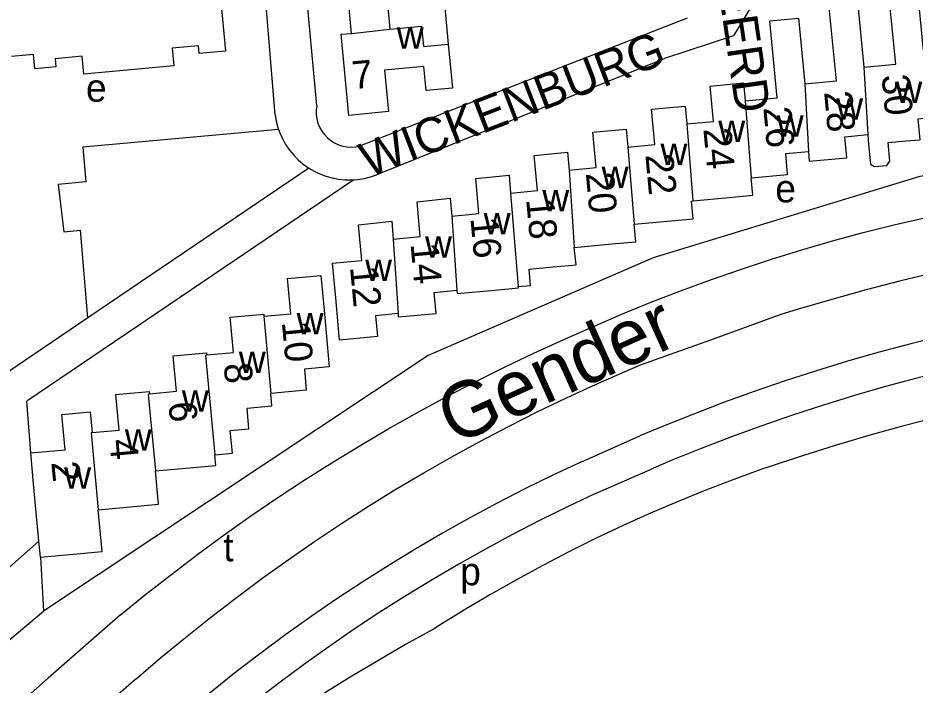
# Model space of a CAD drawing. Extents: x 157794 to 159375, y 380877 to 382306.
# Drawn here: x 158333.5 to 158462.3, y 381095.2 to 381191 of the extents above; entities that cross this region are included whole.
import ezdxf

# ---------------------------------------------------------------- set-up
doc = ezdxf.new("R2010")
doc.units = 0
for name, color, linetype in [('BLT_Basislijn', 7, 'Continuous'), ('BLT_Bebouwing', 7, 'Continuous'), ('BLT_Centroide', 7, 'Continuous'), ('BLT_Huisnummer', 7, 'Continuous'), ('BLT_Huisnummer_ tussenligend', 7, 'Continuous'), ('BLT_Onderverdeling_panden', 7, 'Continuous'), ('BLT_Straatnaam', 7, 'Continuous'), ('BLT_Waternaam_spoorwegen', 7, 'Continuous')]:
    doc.layers.add(name, color=color, linetype=linetype)

msp = doc.modelspace()

# ---------------------------------------------------------------- linework, layer by layer
at = {"layer": 'BLT_Basislijn'}
for p, q in [((158370.4, 381177.07), (158363.87, 381258.34)), ((158376.39, 381178.4), (158369.02, 381258.49)), ((158382.59, 381172.61), (158429.64, 381191.02)), ((158385.64, 381168.75), (158426.34, 381185.15)), ((158375.24, 381169.41), (158343.5, 381147.91)), ((158381.71, 381167.75), (158334.77, 381135.96)), ((158343.5, 381147.91), (158342.47, 381160.51)), ((158343.5, 381147.91), (158330.66, 381139.21)), ((158335.32, 381128.51), (158334.77, 381135.96)), ((158414.31, 381127.2), (158422.8, 381130.94)), ((158416.42, 381122.67), (158424.76, 381126.34)), ((158336.71, 381113.55), (158337.15, 381105.79)), ((158348.23, 381105.23), (158337.82, 381096.13)), ((158337.82, 381096.13), (158303.9, 381066.46)), ((158350.44, 381096.04), (158309.15, 381060.3))]:
    msp.add_line(p, q, dxfattribs=at)
for points in [[(158440.69, 381195.84), (158436.24, 381188.43), (158426.34, 381185.15)], [(158400.9, 381194.66), (158394.62, 381194.06), (158395.27, 381187.21)], [(158505.46, 381182.58), (158505, 381179.52), (158503.68, 381176.79), (158498.04, 381172.99), (158462.98, 381168.23), (158424.71, 381156.55), (158392.37, 381142.52), (158337.15, 381105.79)], [(158376.39, 381178.4), (158376.32, 381177.77), (158376.32, 381177.13), (158376.4, 381176.51), (158376.56, 381175.89), (158376.8, 381175.3), (158377.11, 381174.75), (158377.48, 381174.24), (158377.92, 381173.78), (158378.41, 381173.38), (158378.95, 381173.05), (158379.53, 381172.78), (158380.13, 381172.59), (158380.75, 381172.48), (158381.39, 381172.45), (158382.02, 381172.49), (158382.59, 381172.61)], [(158370.4, 381177.07), (158370.57, 381176.16), (158370.8, 381175.26), (158370.91, 381174.97)], [(158370.91, 381174.97), (158342.82, 381172.41), (158343.25, 381167.44), (158339.27, 381167.06), (158340.08, 381160.29), (158342.47, 381160.51)], [(158370.91, 381174.97), (158371.12, 381174.39), (158371.51, 381173.55), (158371.97, 381172.74), (158372.5, 381171.98), (158373.09, 381171.27), (158373.74, 381170.61), (158374.45, 381170), (158375.24, 381169.41)], [(158375.24, 381169.41), (158376, 381168.99), (158376.83, 381168.59), (158377.7, 381168.26), (158378.59, 381168.01), (158379.51, 381167.84), (158380.43, 381167.74), (158381.36, 381167.73), (158381.71, 381167.75)], [(158381.71, 381167.75), (158382.28, 381167.79), (158383.2, 381167.94), (158384.1, 381168.16), (158384.97, 381168.46), (158385.64, 381168.75)], [(158416.12, 381146.68), (158420.31, 381148.48), (158424.53, 381150.2), (158428.78, 381151.85), (158433.06, 381153.42), (158437.37, 381154.92), (158441.7, 381156.34), (158446.06, 381157.69), (158450.43, 381158.96), (158454.84, 381160.15), (158459.26, 381161.26), (158463.7, 381162.3), (158468.15, 381163.26), (158472.63, 381164.14), (158474.4, 381164.48)], [(158507.52, 381162.93), (158495.6, 381160.02), (158490.51, 381159.28), (158485.43, 381158.47), (158480.37, 381157.57), (158475.32, 381156.6), (158470.29, 381155.55), (158465.27, 381154.42), (158460.27, 381153.21), (158455.29, 381151.93), (158450.33, 381150.57), (158445.39, 381149.13), (158443.03, 381148.41)], [(158503.28, 381151.64), (158498.61, 381151.12), (158493.94, 381150.53), (158489.29, 381149.86), (158484.65, 381149.11), (158480.02, 381148.28), (158475.41, 381147.38), (158470.82, 381146.39), (158466.24, 381145.33), (158461.68, 381144.19), (158457.14, 381142.97), (158452.62, 381141.67), (158448.13, 381140.3), (158443.66, 381138.85), (158439.21, 381137.33), (158434.79, 381135.73), (158430.4, 381134.05), (158426.04, 381132.3), (158422.8, 381130.94)], [(158443.03, 381148.41), (158432.95, 381144.72), (158422.84, 381141.1), (158422.54, 381141)], [(158348.23, 381105.23), (158351.87, 381108.2), (158355.56, 381111.11), (158359.3, 381113.95), (158363.08, 381116.73), (158366.92, 381119.45), (158370.8, 381122.1), (158374.72, 381124.68), (158378.69, 381127.2), (158382.7, 381129.64), (158386.75, 381132.02), (158390.84, 381134.33), (158394.97, 381136.57), (158399.14, 381138.74), (158403.34, 381140.84), (158407.58, 381142.86), (158411.85, 381144.82), (158416.12, 381146.68)], [(158503.78, 381146.66), (158499.15, 381146.15), (158494.53, 381145.57), (158489.92, 381144.9), (158485.32, 381144.15), (158480.74, 381143.33), (158476.17, 381142.43), (158471.62, 381141.45), (158467.08, 381140.39), (158462.57, 381139.25), (158458.07, 381138.04), (158453.6, 381136.74), (158449.14, 381135.38), (158444.72, 381133.93), (158440.31, 381132.41), (158435.94, 381130.82), (158431.59, 381129.15), (158427.27, 381127.4), (158424.76, 381126.34)], [(158350.44, 381096.04), (158353.95, 381099.05), (158357.52, 381101.99), (158361.14, 381104.88), (158364.8, 381107.71), (158368.52, 381110.47), (158372.28, 381113.16), (158376.08, 381115.79), (158379.93, 381118.36), (158383.83, 381120.86), (158387.77, 381123.29), (158391.75, 381125.65), (158395.77, 381127.94), (158399.83, 381130.16), (158403.93, 381132.31), (158408.06, 381134.39), (158412.23, 381136.4), (158416.43, 381138.34), (158420.67, 381140.2), (158422.54, 381141)], [(158500, 381140.31), (158495.01, 381139.59), (158490.04, 381138.79), (158485.07, 381137.91), (158480.13, 381136.95), (158475.2, 381135.91), (158470.28, 381134.8), (158465.39, 381133.61), (158460.51, 381132.33), (158455.65, 381130.99), (158450.82, 381129.56), (158446.01, 381128.06), (158441.22, 381126.48), (158440.32, 381126.17)], [(158414.31, 381127.2), (158410.29, 381125.31), (158406.28, 381123.33), (158402.31, 381121.28), (158398.37, 381119.17), (158394.47, 381116.98), (158390.62, 381114.72), (158386.8, 381112.4), (158383.02, 381110), (158379.29, 381107.54), (158375.61, 381105.01), (158371.97, 381102.42), (158368.37, 381099.76), (158364.83, 381097.04), (158361.33, 381094.26), (158357.89, 381091.41), (158355.97, 381089.78)], [(158440.32, 381126.17), (158436.28, 381124.7), (158432.26, 381123.16), (158428.28, 381121.54), (158424.32, 381119.84), (158420.4, 381118.08), (158416.52, 381116.24), (158412.66, 381114.33), (158408.84, 381112.34), (158405.07, 381110.29), (158401.32, 381108.17), (158397.62, 381105.97), (158393.96, 381103.71), (158393.15, 381103.2)], [(158416.42, 381122.67), (158412.42, 381120.78), (158408.45, 381118.83), (158404.52, 381116.8), (158400.62, 381114.7), (158396.77, 381112.53), (158392.95, 381110.29), (158389.18, 381107.98), (158385.44, 381105.61), (158381.75, 381103.17), (158378.11, 381100.66), (158374.51, 381098.08), (158370.96, 381095.45), (158367.45, 381092.74), (158364, 381089.98), (158360.6, 381087.15), (158359.23, 381085.99)], [(158269.57, 381121.95), (158259.53, 381113.33), (158258.83, 381112.37), (158289.77, 381076.36), (158291.12, 381075.66), (158336.49, 381115.85)], [(158289.99, 381065.95), (158304.19, 381078.05), (158337.15, 381105.79)], [(158393.15, 381103.2), (158389.13, 381100.97), (158385.14, 381098.66), (158381.19, 381096.29), (158377.28, 381093.85), (158373.42, 381091.34), (158369.6, 381088.76), (158365.82, 381086.12), (158362.1, 381083.42), (158358.42, 381080.65), (158354.79, 381077.81), (158351.2, 381074.92), (158347.67, 381071.96), (158347.23, 381071.58)]]:
    msp.add_lwpolyline(points, dxfattribs=at)
at = {"layer": 'BLT_Bebouwing'}
for p, q in [((158381.38, 381188.78), (158380.33, 381200.13)), ((158336.71, 381113.55), (158336.49, 381115.85))]:
    msp.add_line(p, q, dxfattribs=at)
for points in [[(158361.87, 381201.47), (158363.28, 381186.21), (158359.53, 381185.86), (158359.42, 381186.98), (158355.61, 381186.63), (158355.85, 381184.09), (158342.94, 381182.9), (158342.7, 381185.51), (158338.81, 381185.14), (158338.92, 381183.98), (158335.91, 381183.7), (158335.72, 381185.74), (158332.56, 381185.44)], [(158391.9, 381201.1), (158392.39, 381195.68), (158386.36, 381195.13), (158386.89, 381189.37)], [(158454.95, 381183.93), (158459.52, 381184.37), (158458.46, 381195.37), (158462.54, 381195.77), (158463.46, 381186.32)], [(158446.46, 381181.53), (158451.03, 381181.96), (158449.94, 381192.98), (158454.02, 381193.37), (158454.95, 381183.93)], [(158437.91, 381179.09), (158442.49, 381179.52), (158441.45, 381190.57), (158445.55, 381190.96), (158446.46, 381181.53)], [(158386.89, 381189.37), (158391.45, 381189.79), (158391.72, 381186.89), (158395.27, 381187.21)], [(158380.99, 381176.99), (158379.88, 381188.64), (158381.38, 381188.78)], [(158395.27, 381187.21), (158395.86, 381180.91), (158392.1, 381180.57), (158391.78, 381184.01), (158386.14, 381183.5), (158386.68, 381177.55), (158380.99, 381176.99)], [(158429.52, 381175.76), (158433.36, 381176.12), (158432.89, 381181.2), (158437.69, 381181.66), (158437.91, 381179.09)], [(158421.07, 381172.45), (158424.95, 381172.8), (158424.48, 381177.89), (158429.28, 381178.33), (158429.52, 381175.76)], [(158455.5, 381174.23), (158455.63, 381172.82), (158455.89, 381169.98), (158456.47, 381169.64), (158458.23, 381169.81), (158458.7, 381170.42), (158458.44, 381173.08), (158461.03, 381173.32), (158463.02, 381173.5), (158462.74, 381176.51), (158464.03, 381176.63)], [(158412.65, 381169.13), (158416.52, 381169.49), (158416.04, 381174.56), (158420.84, 381175.02), (158421.07, 381172.45)], [(158446.98, 381171.82), (158447.11, 381170.42), (158452.52, 381170.92), (158452.24, 381173.93), (158455.5, 381174.23)], [(158404.23, 381165.84), (158408.1, 381166.19), (158407.62, 381171.24), (158412.42, 381171.72), (158412.65, 381169.13)], [(158438.77, 381168.03), (158444.01, 381168.51), (158443.74, 381171.52), (158446.98, 381171.82)], [(158395.8, 381162.53), (158399.67, 381162.89), (158399.22, 381167.93), (158404.02, 381168.39), (158404.23, 381165.84)], [(158430.38, 381164.7), (158435.62, 381165.2), (158439.01, 381165.52), (158438.77, 381168.03)], [(158387.38, 381159.23), (158391.24, 381159.58), (158390.82, 381164.59), (158395.57, 381165.1), (158395.8, 381162.53)], [(158421.97, 381161.38), (158430.44, 381162.15), (158430.21, 381164.68), (158430.38, 381164.7)], [(158388.06, 381148.52), (158384.81, 381148.22), (158385.09, 381145.21), (158379.67, 381144.71), (158379.11, 381150.78), (158378.65, 381155.76), (158382.86, 381156.16), (158382.38, 381161.25), (158387.15, 381161.81), (158387.38, 381159.23)], [(158413.34, 381158.04), (158418.77, 381158.53), (158422.22, 381158.85), (158421.97, 381161.38)], [(158405.33, 381152.42), (158407.08, 381152.58), (158406.87, 381154.9), (158410.36, 381155.22), (158413.62, 381155.53), (158413.34, 381158.04)], [(158368.8, 381148.14), (158372.65, 381148.49), (158372.19, 381153.54), (158376.99, 381153.98), (158377.45, 381149), (158378.19, 381140.86), (158374.61, 381140.53), (158374.88, 381137.52), (158369.8, 381137.06)], [(158388.06, 381148.52), (158388.1, 381148.04), (158393.52, 381148.55), (158393.24, 381151.57), (158396.49, 381151.87)], [(158396.49, 381151.87), (158396.53, 381151.39), (158401.94, 381151.89), (158405.35, 381152.21), (158405.33, 381152.42)], [(158360.59, 381142.59), (158364.44, 381142.94), (158363.98, 381148.02), (158368.77, 381148.46), (158368.8, 381148.14)], [(158352.38, 381137.01), (158356.23, 381137.36), (158355.77, 381142.45), (158360.56, 381142.89), (158360.59, 381142.59)], [(158344.14, 381131.43), (158348.02, 381131.78), (158347.56, 381136.88), (158352.35, 381137.32), (158352.38, 381137.01)], [(158361.74, 381128.22), (158364.28, 381128.45), (158363.98, 381131.71), (158366.66, 381131.95), (158366.38, 381134.95), (158369.96, 381135.28), (158369.8, 381137.06)], [(158335.32, 381128.51), (158340.25, 381128.96), (158339.78, 381134.05), (158343.87, 381134.42), (158344.14, 381131.43)], [(158336.49, 381115.85), (158335.78, 381123.53), (158335.32, 381128.51)], [(158353.23, 381125.92), (158361.9, 381126.71), (158361.74, 381128.22)], [(158345.01, 381120.35), (158353.66, 381121.14), (158353.23, 381125.92)], [(158336.71, 381113.55), (158345.56, 381114.36), (158345.01, 381120.35)]]:
    msp.add_lwpolyline(points, dxfattribs=at)
at = {"layer": 'BLT_Onderverdeling_panden'}
for p, q in [((158381.38, 381188.78), (158386.89, 381189.37)), ((158454.95, 381183.93), (158455.5, 381174.23)), ((158446.46, 381181.53), (158446.98, 381171.82)), ((158437.91, 381179.09), (158438.77, 381168.03)), ((158429.52, 381175.76), (158430.38, 381164.7)), ((158421.07, 381172.45), (158421.97, 381161.38)), ((158412.65, 381169.13), (158413.34, 381158.04)), ((158404.23, 381165.84), (158405.33, 381152.42)), ((158395.8, 381162.53), (158396.49, 381151.87)), ((158387.38, 381159.23), (158388.06, 381148.52)), ((158368.8, 381148.14), (158369.8, 381137.06))]:
    msp.add_line(p, q, dxfattribs=at)
for points in [[(158360.59, 381142.59), (158360.43, 381142.48), (158361.74, 381128.22)], [(158352.38, 381137.01), (158352.2, 381136.89), (158353.23, 381125.92)], [(158344.14, 381131.43), (158343.99, 381131.41), (158345.01, 381120.35)]]:
    msp.add_lwpolyline(points, dxfattribs=at)

# ---------------------------------------------------------------- texts
at = {"layer": 'BLT_Centroide'}
for s, p in [('w', (158387.88, 381186.56)), ('e', (158343.25, 381178.95)), ('w', (158459.48, 381178.78)), ('w', (158450.98, 381176.38)), ('w', (158434.05, 381173.17)), ('w', (158442.44, 381173.94)), ('w', (158425.75, 381169.86)), ('w', (158417.3, 381166.55)), ('e', (158442.23, 381164.49)), ('w', (158408.78, 381163.2)), ('w', (158400.36, 381159.89)), ('w', (158391.94, 381156.56)), ('w', (158383.34, 381153.22)), ('w', (158373.5, 381145.53)), ('w', (158365.2, 381139.97)), ('w', (158357.02, 381134.42)), ('w', (158348.83, 381128.84)), ('w', (158340.12, 381123.36)), ('t', (158362.98, 381112.94)), ('p', (158396.98, 381109.49))]:
    msp.add_text(s, height=4, dxfattribs=at).set_placement(p)
at = {"layer": 'BLT_Huisnummer'}
for s, rotation, p in [('7', 5.227, (158381.61, 381180.75)), ('30', 275.2953, (158457.49, 381182.74)), ('26', 275.2953, (158440.51, 381178.1)), ('22', 275.2953, (158423.57, 381171.33)), ('18', 275.2953, (158406.45, 381164.95)), ('14', 275.2953, (158389.85, 381158.53)), ('10', 275.2953, (158371.37, 381147.3)), ('6', 275.2953, (158355.08, 381135.73)), ('2', 275.2953, (158338.27, 381127.16))]:
    msp.add_text(s, height=4, rotation=rotation, dxfattribs=at).set_placement(p)
at = {"layer": 'BLT_Huisnummer_ tussenligend'}
for s, p in [('28', (158449.24, 381180.35)), ('24', (158431.9, 381175.05)), ('20', (158415.02, 381168.69)), ('16', (158398.45, 381162.23)), ('12', (158381.16, 381155.22)), ('8', (158363.02, 381141.28)), ('4', (158346.6, 381130.35))]:
    msp.add_text(s, height=4, rotation=275.2953, dxfattribs=at).set_placement(p)
at = {"layer": 'BLT_Straatnaam'}
for s, rotation, p in [('OUD AMELISWEERD', 278.1362, (158427.27, 381242.58)), ('WICKENBURG', 21.0531, (158383.83, 381168.03))]:
    msp.add_text(s, height=5, rotation=rotation, dxfattribs=at).set_placement(p)
at = {"layer": 'BLT_Waternaam_spoorwegen'}
msp.add_text('Gender', height=8, rotation=24.2296, dxfattribs=at).set_placement((158396.1, 381129.55))

doc.saveas('drawing.dxf')
